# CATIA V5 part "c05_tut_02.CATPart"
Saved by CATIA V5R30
Part number: Part1
Bounding box of the stored display mesh (mm): x -20 to 5, y -42.072 to 42.072, z 0 to 101.82
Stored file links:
  D:\PROJECTS\CATIA V56R 2020\Resources\c05_catia_v5_6r2020_tut\c05_tut_02.CATPart
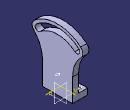
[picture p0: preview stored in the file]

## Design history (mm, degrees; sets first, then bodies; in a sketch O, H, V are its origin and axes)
Body1 (main body)
  Sketch1 on yz-plane, origin (0, 0, 0), H (0, 1, 0), V (0, 0, 1)
    point P1 (-25, 0)
    line L1 (-25, 0) -> (25, 0)
    point P2 (25, 0)
    line L2 (-25, 0) -> (-25, 38.3145)
    point P3 (-25, 38.3145)
    arc A1 centre (0, 42) radius 60 from (38.5673, 87.9627) to (-38.5673, 87.9627) ccw
    point P4 (0, 42)
    axis line L3 (0, 42) -> (-54.0665, 106.434)
    point P5 (-54.0665, 106.434)
    point P6 (54.0665, 106.434)
    point P7 (0, 42)
    construction line L4 (0, 42) -> (54.0665, 106.434)
    point P8 (-38.5673, 87.9627)
    point P9 (38.5673, 87.9627)
    arc A2 centre (-32.1394, 80.3022) radius 10 from (-38.5673, 87.9627) to (-39.2828, 73.3043) ccw
    point P10 (-32.1394, 80.3022)
    arc A3 centre (32.1394, 80.3022) radius 10 from (38.5673, 87.9627) to (39.2828, 73.3043) cw
    arc A4 centre (-75, 38.3145) radius 50 from (-25, 38.3145) to (-39.2828, 73.3043) ccw
    arc A5 centre (75, 38.3145) radius 50 from (25, 38.3145) to (39.2828, 73.3043) cw
    point P14 (25, 38.3145)
    point P15 (25, 0)
    line L5 (25, 0) -> (25, 38.3145)
    point P17 (25, 38.3145)
    length L1 = 50
    angle L4 L3 = 80
    radius A1 = 60
    radius A2 = 10
    radius A5 = 50
    distance P4 L1 = 42
    coincidence: P1 H, P4 V, L3 P8, L4 P9, P10 L3, L5 P17, P2 P15, P14 P17
    horizontal: L1 H
    symmetry: P2 P1 V, P5 P6 V, P4 P7 V, L3 L4 V, A2 A3 V, A4 A5 V, P3 P14 V, P1 P15 V, L2 L5 V
    vertical: L2 V
    tangency: A2 A1, A4 A2, A4 L2, A5 A3, L5 A5
  Pad1: profile Sketch1, direction (1, 0, 0), length 5, mirrored extent
  Sketch2 on start face of Pad1, origin (-5, 0, 0), H (0, -1, 0), V (0, 0, 1)
    construction arc A1 centre (0, 42) radius 50 from (32.1394, 80.3022) to (-32.1394, 80.3022) ccw
    point P1 (0, 42)
    arc A2 centre (32.1394, 80.3022) radius 5 from (35.3533, 84.1324) to (28.9254, 76.472) cw
    arc A3 centre (-32.1394, 80.3022) radius 5 from (-28.9254, 76.472) to (-35.3533, 84.1324) cw
    arc A4 centre (0, 42) radius 45 from (28.9254, 76.472) to (-28.9254, 76.472) ccw
    arc A5 centre (0, 42) radius 55 from (-35.3533, 84.1324) to (35.3533, 84.1324) cw
    construction line L1 (-32.1394, 80.3022) -> (0, 42)
    construction line L2 (0, 42) -> (32.1394, 80.3022)
    radius A3 = 5
    radius A1 = 50
    angle L2 L1 = 80
    angle L2 V = 40
    distance P1 H = 42
    coincidence: P1 V
    tangency: A4 A3, A3 A5, A5 A2, A2 A4
    concentricity: A4 P1, A5 P1
  Pocket1: profile Sketch2, direction (1, 0, 0), through (limit type 6)
  Sketch3 on start face of Pad1, origin (-5, 0, 0), H (0, 1, 0), V (0, 0, 1)
    line L1 (-25, 10) -> (25, 10)
    line L2 (25, 10) -> (25, 0)
    line L3 (25, 0) -> (-25, 0)
    line L4 (-25, 0) -> (-25, 10)
    point P3 (25, 0)
    reference projected line E1 (25, 0) -> (25, 38.3145) from edge [face of Pad1 from Sketch1.L5 | end face of Pad1]
    reference projected line E2 (-25, 38.3145) -> (-25, 0) from edge [face of Pad1 from Sketch1.L2 | end face of Pad1]
    length L2 = 10
    horizontal: L1 H, L3 H
    vertical: L2 V, L4 V
    coincidence: P3 H, L2 E1, L4 E2
  Pad2: profile Sketch3, direction (-1, 0, 0), length 15
  Sketch4 on face of Pad2 from Sketch3.L1, origin (0, 0, 10), H (1, 0, 0), V (0, 1, 0)
    circle A1 centre (-14, 19) radius 2.5
    point P1 (-14, 19)
    reference projected line E1 (-5, 25) -> (-20, 25) from edge [face of Pad2 | face of Pad2 from Sketch3.L1]
    reference projected line E2 (-20, 25) -> (-20, -25) from edge [end face of Pad2 | face of Pad2 from Sketch3.L1]
    circle A2 centre (-14, -19) radius 2.5
    radius A1 = 2.5
    distance E1 P1 = 6
    distance E2 P1 = 6
    symmetry: A1 A2 H
  Pocket2: profile Sketch4, direction (0, 0, -1), through (limit type 3)
  Sketch5 on start face of Pad1, origin (-5, 0, 0), H (0, -1, 0), V (0, 0, 1)
    circle A1 centre (0, 42) radius 11
    point P1 (0, 42)
    circle A2 centre (0, 42) radius 4
    reference projected line E1 (25, 0) -> (-25, 0) from edge [end face of Pad2 | face of Pad2]
    radius A1 = 11
    radius A2 = 4
    distance P1 E1 = 42
    coincidence: P1 V
  Pad3: profile Sketch5, direction (-1, 0, 0), length 9
Current feature: Pocket2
